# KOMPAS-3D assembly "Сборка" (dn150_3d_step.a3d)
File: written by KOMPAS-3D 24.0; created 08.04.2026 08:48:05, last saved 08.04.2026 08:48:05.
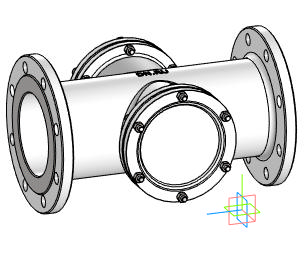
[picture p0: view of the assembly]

Document properties: Автор: Main; Полное имя файла: D:\DN.ru Аутсерс\Стекло смотровое DN.ru\Исходники\Стекло смотровое DN.ru SG2-34G-F тип В ГОСТ 21836-2021 Ду150 Ру16, углеродистая сталь, фланцевое\dn150_3d_step.a3d

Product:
- Component [detail]: Деталь  | qty 1  | Автор: Main; source file: ДетальДеталь.m3d
- Component [detail]: Стекло  | qty 2  | Автор: Main; source file: СтеклоСтекло.m3d
- Component [detail]: ANSI B18.2.4.2M - M10x1,5 - 16  | designation ANSI B18.2.4.2M - M10x1,5  | qty 1  | Автор: Main; source file: ANSI B18.2.4.2M - M10x1,5ANSI B18.2.4.2M - M10x1,5 - 16.m3d
- Component [detail]: ANSI B18.2.4.2M - M10x1,5 - 16  | designation ANSI B18.2.4.2M - M10x1,5  | qty 23  | Комментарий: Типы метрических   шестигранных гаек   2; Автор: Main; additional columns: Сталь, мягкая; source file: ANSI B18.2.4.2M - M10x1,5ANSI B18.2.4.2M - M10x1,5 - 16.m3d
- Part/product: Сборка

Referenced files in D:\DN.ru Аутсерс\Стекло смотровое DN.ru\Исходники\Стекло смотровое DN.ru SG2-34G-F тип В ГОСТ 21836-2021 Ду150 Ру16, углеродистая сталь, фланцевое\: ДетальДеталь.m3d, СтеклоСтекло.m3d, ANSI B18.2.4.2M - M10x1,5ANSI B18.2.4.2M - M10x1,5 - 16.m3d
